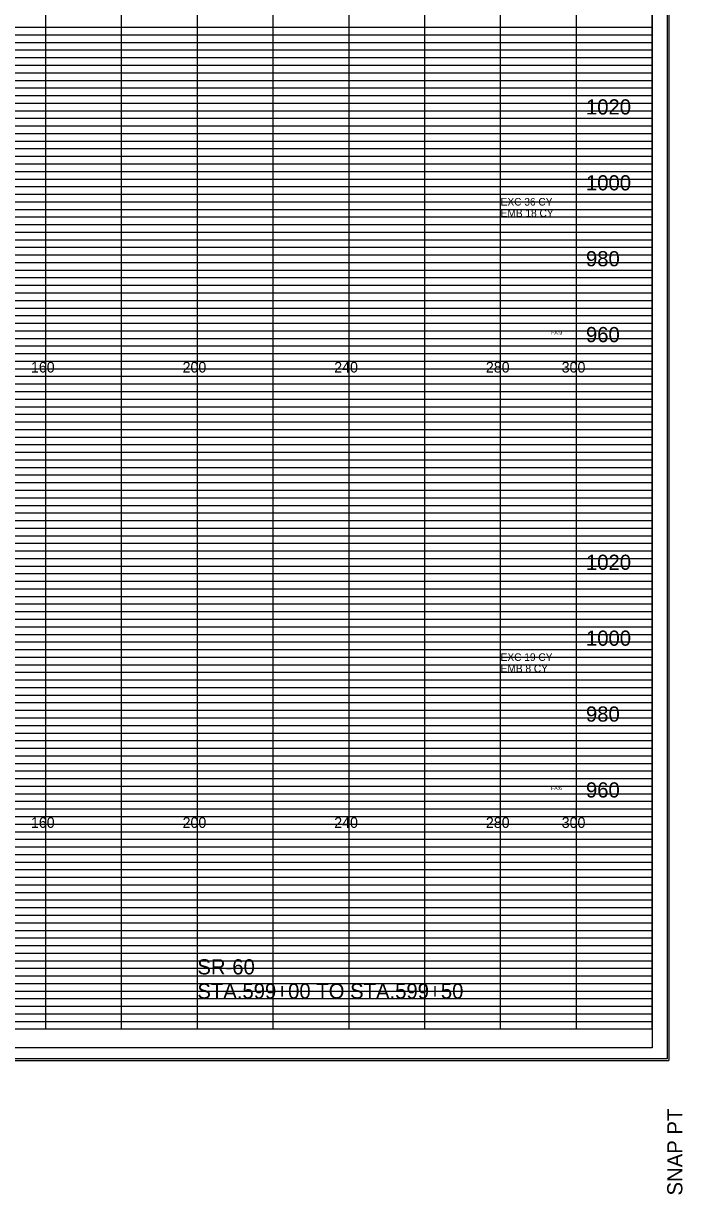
# Model space of a CAD drawing. Extents: x 2313580 to 2322968, y 282099 to 303247.
# Drawn here: x 2316564.2 to 2316738.1, y 287544 to 287852.7 of the extents above; entities that cross this region are included whole.
import ezdxf

# ---------------------------------------------------------------- set-up
doc = ezdxf.new("R2010")
doc.units = 0
for name, color, linetype in [('DESIGN - EARTHWORK - Excavation Limit Lines', 7, 'Continuous'), ('DESIGN - SHEET - Corner Text', 7, 'Continuous'), ('DESIGN - SHEET - Light Grid', 7, 'Continuous'), ('DESIGN - SHEET - Linework', 7, 'Continuous'), ('DESIGN - SHEET - Plot Shape', 7, 'Continuous'), ('DESIGN - TYPICAL - Text', 7, 'Continuous'), ('Prop_ CL text', 7, 'Continuous')]:
    doc.layers.add(name, color=color, linetype=linetype)

msp = doc.modelspace()

# ---------------------------------------------------------------- linework, layer by layer
at = {"layer": 'DESIGN - SHEET - Light Grid'}
for p, q in [((2316410.08, 287851.67), (2316570.08, 287851.67)), ((2316570.08, 287851.67), (2316730.08, 287851.67)), ((2316410.08, 287849.67), (2316570.08, 287849.67)), ((2316570.08, 287849.67), (2316730.08, 287849.67)), ((2316410.08, 287845.67), (2316570.08, 287845.67)), ((2316570.08, 287845.67), (2316730.08, 287845.67)), ((2316410.08, 287843.67), (2316570.08, 287843.67)), ((2316410.08, 287841.67), (2316570.08, 287841.67)), ((2316570.08, 287843.67), (2316730.08, 287843.67)), ((2316570.08, 287841.67), (2316730.08, 287841.67)), ((2316410.08, 287839.67), (2316570.08, 287839.67)), ((2316570.08, 287839.67), (2316730.08, 287839.67)), ((2316410.08, 287837.67), (2316570.08, 287837.67)), ((2316410.08, 287835.67), (2316570.08, 287835.67)), ((2316570.08, 287837.67), (2316730.08, 287837.67)), ((2316570.08, 287835.67), (2316730.08, 287835.67)), ((2316410.08, 287833.67), (2316570.08, 287833.67)), ((2316410.08, 287831.67), (2316570.08, 287831.67)), ((2316570.08, 287833.67), (2316730.08, 287833.67)), ((2316570.08, 287831.67), (2316730.08, 287831.67)), ((2316410.08, 287829.67), (2316570.08, 287829.67)), ((2316570.08, 287829.67), (2316730.08, 287829.67)), ((2316410.08, 287825.67), (2316570.08, 287825.67)), ((2316570.08, 287825.67), (2316730.08, 287825.67)), ((2316410.08, 287823.67), (2316570.08, 287823.67)), ((2316570.08, 287823.67), (2316730.08, 287823.67)), ((2316410.08, 287821.67), (2316570.08, 287821.67)), ((2316410.08, 287819.67), (2316570.08, 287819.67)), ((2316570.08, 287821.67), (2316730.08, 287821.67)), ((2316570.08, 287819.67), (2316730.08, 287819.67)), ((2316410.08, 287817.67), (2316570.08, 287817.67)), ((2316570.08, 287817.67), (2316730.08, 287817.67)), ((2316410.08, 287815.67), (2316570.08, 287815.67)), ((2316410.08, 287813.67), (2316570.08, 287813.67)), ((2316570.08, 287815.67), (2316730.08, 287815.67)), ((2316570.08, 287813.67), (2316730.08, 287813.67)), ((2316410.08, 287811.67), (2316570.08, 287811.67)), ((2316570.08, 287811.67), (2316730.08, 287811.67)), ((2316410.08, 287809.67), (2316570.08, 287809.67)), ((2316570.08, 287809.67), (2316730.08, 287809.67)), ((2316410.08, 287805.67), (2316570.08, 287805.67)), ((2316570.08, 287805.67), (2316730.08, 287805.67)), ((2316410.08, 287803.67), (2316570.08, 287803.67)), ((2316410.08, 287801.67), (2316570.08, 287801.67)), ((2316570.08, 287803.67), (2316730.08, 287803.67)), ((2316570.08, 287801.67), (2316730.08, 287801.67)), ((2316410.08, 287799.67), (2316570.08, 287799.67)), ((2316410.08, 287797.67), (2316570.08, 287797.67)), ((2316570.08, 287799.67), (2316730.08, 287799.67)), ((2316570.08, 287797.67), (2316730.08, 287797.67)), ((2316410.08, 287795.67), (2316570.08, 287795.67)), ((2316570.08, 287795.67), (2316730.08, 287795.67)), ((2316410.08, 287793.67), (2316570.08, 287793.67)), ((2316410.08, 287791.67), (2316570.08, 287791.67)), ((2316570.08, 287793.67), (2316730.08, 287793.67)), ((2316570.08, 287791.67), (2316730.08, 287791.67)), ((2316410.08, 287789.67), (2316570.08, 287789.67)), ((2316570.08, 287789.67), (2316730.08, 287789.67)), ((2316410.08, 287785.67), (2316570.08, 287785.67)), ((2316570.08, 287785.67), (2316730.08, 287785.67)), ((2316410.08, 287783.67), (2316570.08, 287783.67)), ((2316570.08, 287783.67), (2316730.08, 287783.67)), ((2316410.08, 287781.67), (2316570.08, 287781.67)), ((2316410.08, 287779.67), (2316570.08, 287779.67)), ((2316570.08, 287781.67), (2316730.08, 287781.67)), ((2316570.08, 287779.67), (2316730.08, 287779.67)), ((2316410.08, 287777.67), (2316570.08, 287777.67)), ((2316570.08, 287777.67), (2316730.08, 287777.67)), ((2316410.08, 287775.67), (2316570.08, 287775.67)), ((2316410.08, 287773.67), (2316570.08, 287773.67)), ((2316570.08, 287775.67), (2316730.08, 287775.67)), ((2316570.08, 287773.67), (2316730.08, 287773.67)), ((2316410.08, 287771.67), (2316570.08, 287771.67)), ((2316570.08, 287771.67), (2316730.08, 287771.67)), ((2316410.08, 287769.67), (2316570.08, 287769.67)), ((2316570.08, 287769.67), (2316730.08, 287769.67)), ((2316410.08, 287765.67), (2316570.08, 287765.67)), ((2316410.08, 287763.67), (2316570.08, 287763.67)), ((2316570.08, 287765.67), (2316730.08, 287765.67)), ((2316570.08, 287763.67), (2316730.08, 287763.67)), ((2316410.08, 287761.67), (2316570.08, 287761.67)), ((2316570.08, 287761.67), (2316730.08, 287761.67)), ((2316410.08, 287759.67), (2316570.08, 287759.67)), ((2316410.08, 287757.67), (2316570.08, 287757.67)), ((2316570.08, 287759.67), (2316730.08, 287759.67)), ((2316570.08, 287757.67), (2316730.08, 287757.67)), ((2316410.08, 287755.67), (2316570.08, 287755.67)), ((2316570.08, 287755.67), (2316730.08, 287755.67)), ((2316410.08, 287753.67), (2316570.08, 287753.67)), ((2316410.08, 287751.67), (2316570.08, 287751.67)), ((2316570.08, 287753.67), (2316730.08, 287753.67)), ((2316570.08, 287751.67), (2316730.08, 287751.67)), ((2316410.08, 287749.67), (2316570.08, 287749.67)), ((2316570.08, 287749.67), (2316730.08, 287749.67)), ((2316410.08, 287745.67), (2316570.08, 287745.67)), ((2316570.08, 287745.67), (2316730.08, 287745.67)), ((2316410.08, 287743.67), (2316570.08, 287743.67)), ((2316570.08, 287743.67), (2316730.08, 287743.67)), ((2316410.08, 287741.67), (2316570.08, 287741.67)), ((2316410.08, 287739.67), (2316570.08, 287739.67)), ((2316570.08, 287741.67), (2316730.08, 287741.67)), ((2316570.08, 287739.67), (2316730.08, 287739.67)), ((2316410.08, 287737.67), (2316570.08, 287737.67)), ((2316570.08, 287737.67), (2316730.08, 287737.67)), ((2316410.08, 287735.67), (2316570.08, 287735.67)), ((2316410.08, 287733.67), (2316570.08, 287733.67)), ((2316570.08, 287735.67), (2316730.08, 287735.67)), ((2316570.08, 287733.67), (2316730.08, 287733.67)), ((2316410.08, 287731.67), (2316570.08, 287731.67)), ((2316570.08, 287731.67), (2316730.08, 287731.67)), ((2316410.08, 287729.67), (2316570.08, 287729.67)), ((2316570.08, 287729.67), (2316730.08, 287729.67)), ((2316410.08, 287725.67), (2316570.08, 287725.67)), ((2316410.08, 287723.67), (2316570.08, 287723.67)), ((2316570.08, 287725.67), (2316730.08, 287725.67)), ((2316570.08, 287723.67), (2316730.08, 287723.67)), ((2316410.08, 287721.67), (2316570.08, 287721.67)), ((2316570.08, 287721.67), (2316730.08, 287721.67)), ((2316410.08, 287719.67), (2316570.08, 287719.67)), ((2316410.08, 287717.67), (2316570.08, 287717.67)), ((2316570.08, 287719.67), (2316730.08, 287719.67)), ((2316570.08, 287717.67), (2316730.08, 287717.67)), ((2316410.08, 287715.67), (2316570.08, 287715.67)), ((2316570.08, 287715.67), (2316730.08, 287715.67)), ((2316410.08, 287713.67), (2316570.08, 287713.67)), ((2316410.08, 287711.67), (2316570.08, 287711.67)), ((2316570.08, 287713.67), (2316730.08, 287713.67)), ((2316570.08, 287711.67), (2316730.08, 287711.67)), ((2316410.08, 287709.67), (2316570.08, 287709.67)), ((2316570.08, 287709.67), (2316730.08, 287709.67)), ((2316410.08, 287705.67), (2316570.08, 287705.67)), ((2316570.08, 287705.67), (2316730.08, 287705.67)), ((2316410.08, 287703.67), (2316570.08, 287703.67)), ((2316570.08, 287703.67), (2316730.08, 287703.67)), ((2316410.08, 287701.67), (2316570.08, 287701.67)), ((2316410.08, 287699.67), (2316570.08, 287699.67)), ((2316570.08, 287701.67), (2316730.08, 287701.67)), ((2316570.08, 287699.67), (2316730.08, 287699.67)), ((2316410.08, 287697.67), (2316570.08, 287697.67)), ((2316570.08, 287697.67), (2316730.08, 287697.67)), ((2316410.08, 287695.67), (2316570.08, 287695.67)), ((2316410.08, 287693.67), (2316570.08, 287693.67)), ((2316570.08, 287695.67), (2316730.08, 287695.67)), ((2316570.08, 287693.67), (2316730.08, 287693.67)), ((2316410.08, 287691.67), (2316570.08, 287691.67)), ((2316410.08, 287689.67), (2316570.08, 287689.67)), ((2316570.08, 287691.67), (2316730.08, 287691.67)), ((2316570.08, 287689.67), (2316730.08, 287689.67)), ((2316410.08, 287685.67), (2316570.08, 287685.67)), ((2316410.08, 287683.67), (2316570.08, 287683.67)), ((2316570.08, 287685.67), (2316730.08, 287685.67)), ((2316570.08, 287683.67), (2316730.08, 287683.67)), ((2316410.08, 287681.67), (2316570.08, 287681.67)), ((2316570.08, 287681.67), (2316730.08, 287681.67)), ((2316410.08, 287679.67), (2316570.08, 287679.67)), ((2316410.08, 287677.67), (2316570.08, 287677.67)), ((2316570.08, 287679.67), (2316730.08, 287679.67)), ((2316570.08, 287677.67), (2316730.08, 287677.67)), ((2316410.08, 287675.67), (2316570.08, 287675.67)), ((2316570.08, 287675.67), (2316730.08, 287675.67)), ((2316410.08, 287673.67), (2316570.08, 287673.67)), ((2316410.08, 287671.67), (2316570.08, 287671.67)), ((2316570.08, 287673.67), (2316730.08, 287673.67)), ((2316570.08, 287671.67), (2316730.08, 287671.67)), ((2316410.08, 287669.67), (2316570.08, 287669.67)), ((2316570.08, 287669.67), (2316730.08, 287669.67)), ((2316410.08, 287665.67), (2316570.08, 287665.67)), ((2316570.08, 287665.67), (2316730.08, 287665.67)), ((2316410.08, 287663.67), (2316570.08, 287663.67)), ((2316570.08, 287663.67), (2316730.08, 287663.67)), ((2316410.08, 287661.67), (2316570.08, 287661.67)), ((2316410.08, 287659.67), (2316570.08, 287659.67)), ((2316570.08, 287661.67), (2316730.08, 287661.67)), ((2316570.08, 287659.67), (2316730.08, 287659.67)), ((2316410.08, 287657.67), (2316570.08, 287657.67)), ((2316410.08, 287655.67), (2316570.08, 287655.67)), ((2316570.08, 287657.67), (2316730.08, 287657.67)), ((2316570.08, 287655.67), (2316730.08, 287655.67)), ((2316410.08, 287653.67), (2316570.08, 287653.67)), ((2316570.08, 287653.67), (2316730.08, 287653.67)), ((2316410.08, 287651.67), (2316570.08, 287651.67)), ((2316410.08, 287649.67), (2316570.08, 287649.67)), ((2316570.08, 287651.67), (2316730.08, 287651.67)), ((2316570.08, 287649.67), (2316730.08, 287649.67)), ((2316410.08, 287645.67), (2316570.08, 287645.67)), ((2316410.08, 287643.67), (2316570.08, 287643.67)), ((2316570.08, 287645.67), (2316730.08, 287645.67)), ((2316570.08, 287643.67), (2316730.08, 287643.67)), ((2316410.08, 287641.67), (2316570.08, 287641.67)), ((2316570.08, 287641.67), (2316730.08, 287641.67)), ((2316410.08, 287639.67), (2316570.08, 287639.67)), ((2316410.08, 287637.67), (2316570.08, 287637.67)), ((2316570.08, 287639.67), (2316730.08, 287639.67)), ((2316570.08, 287637.67), (2316730.08, 287637.67)), ((2316410.08, 287635.67), (2316570.08, 287635.67)), ((2316570.08, 287635.67), (2316730.08, 287635.67)), ((2316410.08, 287633.67), (2316570.08, 287633.67)), ((2316410.08, 287631.67), (2316570.08, 287631.67)), ((2316570.08, 287633.67), (2316730.08, 287633.67)), ((2316570.08, 287631.67), (2316730.08, 287631.67)), ((2316410.08, 287629.67), (2316570.08, 287629.67)), ((2316570.08, 287629.67), (2316730.08, 287629.67)), ((2316410.08, 287625.67), (2316570.08, 287625.67)), ((2316570.08, 287625.67), (2316730.08, 287625.67)), ((2316410.08, 287623.67), (2316570.08, 287623.67)), ((2316570.08, 287623.67), (2316730.08, 287623.67)), ((2316410.08, 287621.67), (2316570.08, 287621.67)), ((2316410.08, 287619.67), (2316570.08, 287619.67)), ((2316570.08, 287621.67), (2316730.08, 287621.67)), ((2316570.08, 287619.67), (2316730.08, 287619.67)), ((2316410.08, 287617.67), (2316570.08, 287617.67)), ((2316410.08, 287615.67), (2316570.08, 287615.67)), ((2316570.08, 287617.67), (2316730.08, 287617.67)), ((2316570.08, 287615.67), (2316730.08, 287615.67)), ((2316410.08, 287613.67), (2316570.08, 287613.67)), ((2316570.08, 287613.67), (2316730.08, 287613.67)), ((2316410.08, 287611.67), (2316570.08, 287611.67)), ((2316410.08, 287609.67), (2316570.08, 287609.67)), ((2316570.08, 287611.67), (2316730.08, 287611.67)), ((2316570.08, 287609.67), (2316730.08, 287609.67)), ((2316410.08, 287605.67), (2316570.08, 287605.67)), ((2316410.08, 287603.67), (2316570.08, 287603.67)), ((2316570.08, 287605.67), (2316730.08, 287605.67)), ((2316570.08, 287603.67), (2316730.08, 287603.67)), ((2316410.08, 287601.67), (2316570.08, 287601.67)), ((2316570.08, 287601.67), (2316730.08, 287601.67)), ((2316410.08, 287599.67), (2316570.08, 287599.67)), ((2316410.08, 287597.67), (2316570.08, 287597.67)), ((2316570.08, 287599.67), (2316730.08, 287599.67)), ((2316570.08, 287597.67), (2316730.08, 287597.67)), ((2316410.08, 287595.67), (2316570.08, 287595.67)), ((2316570.08, 287595.67), (2316730.08, 287595.67)), ((2316410.08, 287593.67), (2316570.08, 287593.67)), ((2316410.08, 287591.67), (2316570.08, 287591.67)), ((2316570.08, 287593.67), (2316730.08, 287593.67)), ((2316570.08, 287591.67), (2316730.08, 287591.67)), ((2316410.08, 287589.67), (2316570.08, 287589.67)), ((2316570.08, 287589.67), (2316730.08, 287589.67))]:
    msp.add_line(p, q, dxfattribs=at)
at = {"layer": 'DESIGN - SHEET - Linework'}
for p, q in [((2316734.42, 288015.95), (2316734.42, 287579.39)), ((2316570.08, 287587.67), (2316570.08, 288007.67)), ((2316590.08, 287587.67), (2316590.08, 288007.67)), ((2316610.08, 287587.67), (2316610.08, 288007.67)), ((2316630.08, 287587.67), (2316630.08, 288007.67)), ((2316650.08, 287587.67), (2316650.08, 287987.67)), ((2316670.08, 287587.67), (2316670.08, 287987.67)), ((2316690.08, 287587.67), (2316690.08, 287987.67)), ((2316710.08, 287587.67), (2316710.08, 287987.67)), ((2316090.08, 287847.67), (2316730.08, 287847.67)), ((2316090.08, 287827.67), (2316730.08, 287827.67)), ((2316090.08, 287807.67), (2316730.08, 287807.67)), ((2316090.08, 287787.67), (2316730.08, 287787.67)), ((2316090.08, 287767.67), (2316730.08, 287767.67)), ((2316090.08, 287747.67), (2316730.08, 287747.67)), ((2316090.08, 287727.67), (2316730.08, 287727.67)), ((2316090.08, 287707.67), (2316730.08, 287707.67)), ((2316090.08, 287687.67), (2316730.08, 287687.67)), ((2316090.08, 287667.67), (2316730.08, 287667.67)), ((2316090.08, 287647.67), (2316730.08, 287647.67)), ((2316090.08, 287627.67), (2316730.08, 287627.67)), ((2316090.08, 287607.67), (2316730.08, 287607.67)), ((2316053.62, 287579.39), (2316734.42, 287579.39))]:
    msp.add_line(p, q, dxfattribs=at)
msp.add_lwpolyline([(2316090.08, 288007.67), (2316090.08, 287587.67), (2316730.08, 287587.67), (2316730.08, 288007.67), (2316090.08, 288007.67)], dxfattribs=at)
at = {"layer": 'DESIGN - SHEET - Plot Shape'}
for points in [[(2316054.02, 288015.55), (2316734.02, 288015.55), (2316734.02, 287579.79), (2316054.02, 287579.79)], [(2316073.08, 288007.67), (2316730.08, 288007.67), (2316730.08, 287582.67), (2316073.08, 287582.67)]]:
    msp.add_lwpolyline(points, close=True, dxfattribs=at)

# ---------------------------------------------------------------- texts
at = {"layer": 'DESIGN - EARTHWORK - Excavation Limit Lines'}
for s, p in [('EXC 36 CY', (2316690.08, 287804.67)), ('EMB 18 CY', (2316690.08, 287801.67)), ('EXC 19 CY', (2316690.08, 287684.67)), ('EMB 8 CY', (2316690.08, 287681.67))]:
    msp.add_text(s, height=2, dxfattribs=at).set_placement(p)
at = {"layer": 'DESIGN - SHEET - Corner Text'}
msp.add_text('SNAP PT  ', height=4, rotation=90, dxfattribs=at).set_placement((2316738.02, 287543.79))
at = {"layer": 'DESIGN - TYPICAL - Text'}
for s, height, p in [('1020', 4, (2316712.58, 287828.67)), ('1000', 4, (2316712.58, 287808.67)), ('980', 4, (2316712.58, 287788.67)), ('960', 4, (2316712.58, 287768.67)), ('160', 2.8, (2316566.19, 287760.67)), ('200', 2.8, (2316606.19, 287760.67)), ('240', 2.8, (2316646.19, 287760.67)), ('280', 2.8, (2316686.19, 287760.67)), ('300', 2.8, (2316706.19, 287760.67)), ('1020', 4, (2316712.58, 287708.67)), ('1000', 4, (2316712.58, 287688.67)), ('980', 4, (2316712.58, 287668.67)), ('960', 4, (2316712.58, 287648.67)), ('160', 2.8, (2316566.19, 287640.67)), ('200', 2.8, (2316606.19, 287640.67)), ('240', 2.8, (2316646.19, 287640.67)), ('280', 2.8, (2316686.19, 287640.67)), ('300', 2.8, (2316706.19, 287640.67)), ('SR-60', 4, (2316610.08, 287602.05)), ('STA.599+00 TO STA.599+50', 4, (2316610.08, 287595.67))]:
    msp.add_text(s, height=height, dxfattribs=at).set_placement(p)
at = {"layer": 'Prop_ CL text'}
for s, p in [('FA:9', (2316703.4, 287770.67)), ('FA:6', (2316703.35, 287650.67))]:
    msp.add_text(s, height=1, dxfattribs=at).set_placement(p)

doc.saveas('drawing.dxf')
